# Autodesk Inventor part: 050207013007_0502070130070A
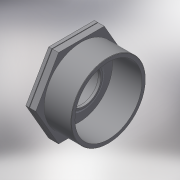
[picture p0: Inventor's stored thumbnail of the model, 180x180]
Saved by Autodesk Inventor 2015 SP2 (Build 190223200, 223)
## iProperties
Created: 2017-05
Part Number: 050207013007_0502070130070A
Material: Generic
Description: PLASSON REDUCING BUSHING 1.1/4"-3/4"
Document SubType Name: Modeling
Designer: KIM
Density: 1 g/cm^3
Appearance: Default
Author: KIM
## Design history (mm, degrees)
derived "050207.ipt"
feature "Solid1::050207.ipt"
tag "TaggingFeature1"
body "Solid1"
other parameters: "d1" = 41.91, "d2" = 46, "d5" = 21, "d8" = 0.37, "d12" = 0, "d15" = 37, "d19" = 0, "d30" = 9.25, "d31" = 4.625, "d33" = 24.117, "d34" = 37.719, "d36" = 2.3, "d37" = 28.9404, "d38" = 24.42, "d39" = 21.7053, "d40" = 2.1, "d41" = 0, "H_" = 37, "R_" = 41.91, "E_" = 46, "l_2" = 21, "Rp_" = 24.117
